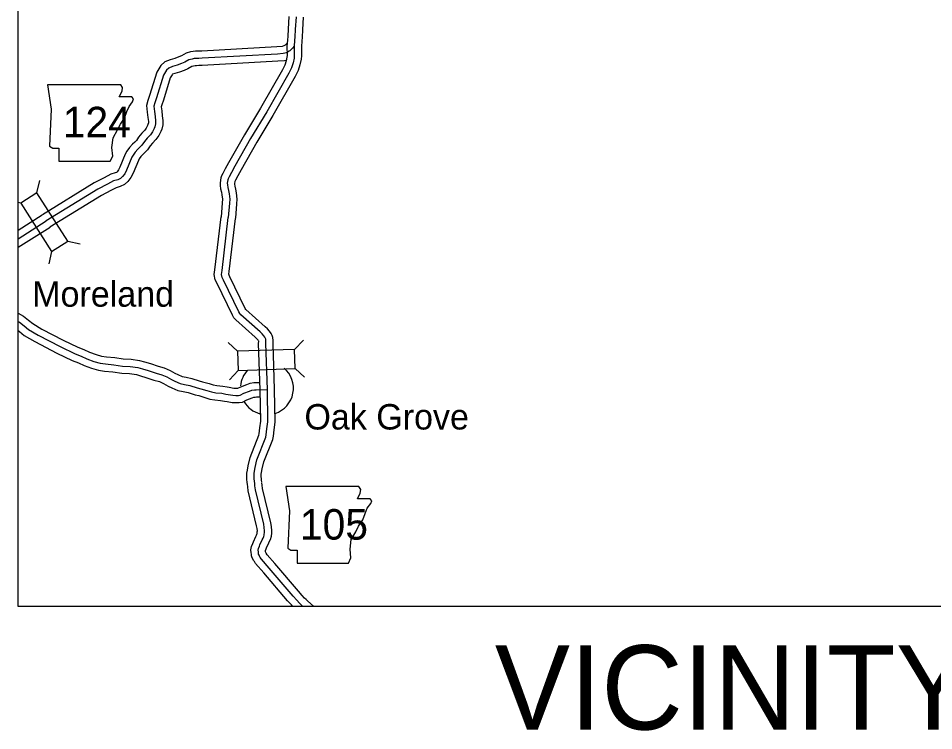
# Model space of a CAD drawing. Extents: x 1373862 to 1376999, y 1168398 to 1170455.
# Drawn here: x 1373884.5 to 1374264.4, y 1169674.5 to 1169970.4 of the extents above; entities that cross this region are included whole.
import ezdxf

# ---------------------------------------------------------------- set-up
doc = ezdxf.new("R2010")
doc.units = 0
for name, color, linetype in [('Level 10', 7, 'Continuous'), ('Level 20', 7, 'Continuous'), ('Level 21', 7, 'Continuous'), ('Level 24', 7, 'Continuous'), ('Level 59', 7, 'Continuous'), ('R_Draft', 7, 'Continuous')]:
    doc.layers.add(name, color=color, linetype=linetype)

msp = doc.modelspace()

# ---------------------------------------------------------------- linework, layer by layer
at = {"layer": 'Level 10'}
for points in [[(1373996.77, 1169971.05), (1373996.45, 1169965.88), (1373996.3, 1169962.9), (1373996.16, 1169961.33), (1373996, 1169958.83), (1373996.05, 1169954.92), (1373996, 1169954.28), (1373995.61, 1169952.66), (1373995.05, 1169950.89), (1373994.13, 1169948.96), (1373985, 1169933.02), (1373978.31, 1169921.99), (1373971.79, 1169910.4), (1373970.35, 1169907.8), (1373969.36, 1169905.9), (1373968.86, 1169904.91), (1373968.56, 1169904.04), (1373968.22, 1169902.08), (1373968.28, 1169900.92), (1373968.46, 1169899.55), (1373968.8, 1169898.18), (1373969, 1169897.06), (1373969.21, 1169895.2), (1373969.09, 1169893.76), (1373968.63, 1169887.8)], [(1374002.77, 1169970.84), (1374002.44, 1169965.54), (1374002.29, 1169962.47), (1374002.14, 1169960.87), (1374002, 1169958.68), (1374002.05, 1169954.73), (1374001.95, 1169953.33), (1374001.39, 1169951.04), (1374000.64, 1169948.7), (1373999.46, 1169946.18), (1373990.17, 1169929.98), (1373983.49, 1169918.96), (1373977.03, 1169907.47), (1373975.63, 1169904.96), (1373974.7, 1169903.16), (1373974.4, 1169902.58), (1373974.39, 1169902.55), (1373974.24, 1169901.7), (1373974.26, 1169901.47), (1373974.36, 1169900.68), (1373974.68, 1169899.42), (1373974.94, 1169897.91), (1373975.23, 1169895.29), (1373975.07, 1169893.28), (1373974.61, 1169887.34)], [(1373996.12, 1169959.97), (1373995.81, 1169959.7), (1373995.26, 1169959.18), (1373995.26, 1169959.18), (1373994.7, 1169958.88), (1373993.97, 1169958.68), (1373991.81, 1169958.52), (1373960.62, 1169956.76), (1373959.29, 1169956.73), (1373958.07, 1169956.68), (1373957.12, 1169956.58), (1373955.95, 1169956.38), (1373954.16, 1169955.9), (1373952.26, 1169954.83), (1373951.09, 1169954.33), (1373949.46, 1169953.73), (1373947.52, 1169953.16), (1373945.35, 1169952.31), (1373943.58, 1169950.78), (1373941.97, 1169947.97), (1373939, 1169938.24), (1373938.29, 1169936.17), (1373937.75, 1169934.18), (1373938.02, 1169931.33), (1373938.25, 1169929.15), (1373938.48, 1169927.56), (1373938.47, 1169926.91), (1373938.31, 1169926.25), (1373938.13, 1169925.85), (1373937.59, 1169924.75), (1373937, 1169923.88), (1373935.69, 1169922.63), (1373934.37, 1169920.97), (1373933.49, 1169919.61), (1373932.82, 1169918.97), (1373931.91, 1169918.08), (1373930.69, 1169916.7), (1373929.54, 1169915.13), (1373928.9, 1169913.9), (1373926.65, 1169908.48), (1373926.13, 1169907.43), (1373925.5, 1169906.64), (1373925.19, 1169906.34), (1373924.71, 1169906.13), (1373922.87, 1169905.6), (1373920.13, 1169904.13), (1373916.04, 1169901.96), (1373894.49, 1169888.74)], [(1373995.59, 1169952.9), (1373994.99, 1169952.73), (1373992.2, 1169952.54), (1373960.86, 1169950.76), (1373959.48, 1169950.73), (1373958.5, 1169950.69), (1373957.94, 1169950.63), (1373957.24, 1169950.51), (1373956.44, 1169950.3), (1373954.91, 1169949.44), (1373953.31, 1169948.75), (1373951.34, 1169948.03), (1373949.47, 1169947.48), (1373948.5, 1169947.1), (1373948.28, 1169946.9), (1373947.51, 1169945.57), (1373944.71, 1169936.39), (1373944.03, 1169934.41), (1373943.83, 1169933.66), (1373943.99, 1169931.92), (1373944.21, 1169929.9), (1373944.49, 1169927.91), (1373944.45, 1169926.11), (1373944.02, 1169924.35), (1373943.59, 1169923.34), (1373942.79, 1169921.72), (1373941.6, 1169919.99), (1373940.13, 1169918.57), (1373939.24, 1169917.46), (1373938.15, 1169915.77), (1373936.99, 1169914.65), (1373936.25, 1169913.94), (1373935.37, 1169912.94), (1373934.65, 1169911.95), (1373934.34, 1169911.35), (1373932.11, 1169905.99), (1373931.22, 1169904.2), (1373929.94, 1169902.58), (1373928.57, 1169901.28), (1373926.76, 1169900.48), (1373925.14, 1169900.01), (1373922.95, 1169898.84), (1373919.02, 1169896.75), (1373897.63, 1169883.63)], [(1373884.49, 1169882.37), (1373894.45, 1169888.71)], [(1373979.64, 1169776.67), (1373979.47, 1169777.75), (1373979.38, 1169778.85), (1373979.34, 1169779.81), (1373979.33, 1169781.5), (1373979.56, 1169782.74), (1373979.83, 1169784.42), (1373980.69, 1169787.93), (1373984.33, 1169797.23), (1373984.46, 1169797.8), (1373984.67, 1169800.2), (1373985.11, 1169803.02), (1373984.87, 1169816.04), (1373984.22, 1169835.35), (1373984.26, 1169836.32), (1373984.22, 1169836.4), (1373984.05, 1169836.64), (1373983.51, 1169837.24), (1373982.85, 1169837.9), (1373974.72, 1169845.12), (1373973.94, 1169845.99), (1373973.37, 1169847.06), (1373966.97, 1169860.25), (1373966.19, 1169861.74), (1373965.82, 1169863.91), (1373966.06, 1169865.91), (1373968.64, 1169887.92)], [(1373985.56, 1169777.64), (1373985.43, 1169778.48), (1373985.37, 1169779.22), (1373985.34, 1169779.94), (1373985.34, 1169780.97), (1373985.47, 1169781.73), (1373985.71, 1169783.23), (1373986.42, 1169786.11), (1373990.08, 1169795.47), (1373990.4, 1169796.87), (1373990.63, 1169799.48), (1373991.12, 1169802.6), (1373990.87, 1169816.19), (1373990.22, 1169835.33), (1373990.27, 1169836.52), (1373990.13, 1169837.85), (1373989.8, 1169838.63), (1373989.42, 1169839.43), (1373988.77, 1169840.38), (1373987.85, 1169841.39), (1373986.96, 1169842.27), (1373978.95, 1169849.39), (1373978.88, 1169849.46), (1373978.71, 1169849.78), (1373972.33, 1169862.95), (1373971.95, 1169863.68), (1373971.88, 1169864.06), (1373972.02, 1169865.2), (1373974.6, 1169887.23)], [(1373884.49, 1169875.26), (1373897.67, 1169883.65)], [(1373884.49, 1169847.96), (1373886.62, 1169846.59), (1373888.77, 1169845), (1373890.46, 1169843.55), (1373894.23, 1169841.31), (1373903.14, 1169836.68), (1373909.19, 1169833.75), (1373911.74, 1169832.81), (1373914.07, 1169831.76), (1373916.76, 1169830.73), (1373919.03, 1169830.08), (1373921.05, 1169829.81), (1373924.54, 1169829.41), (1373928.06, 1169828.93), (1373931.27, 1169828.78), (1373934.75, 1169828.25), (1373936.89, 1169827.68), (1373939.3, 1169826.93), (1373942.54, 1169825.84), (1373945.07, 1169825.15), (1373947.52, 1169824.08), (1373949.42, 1169822.95), (1373950.64, 1169822.41), (1373952.52, 1169821.58), (1373954.12, 1169821.27), (1373956.53, 1169820.75), (1373959.55, 1169819.77), (1373960.97, 1169819.42), (1373963.66, 1169818.64), (1373965.41, 1169818.09), (1373966.86, 1169817.85), (1373969.37, 1169817.6), (1373971.11, 1169817.24), (1373972.05, 1169817.1), (1373973.88, 1169816.8), (1373974.81, 1169816.75), (1373975.63, 1169816.75), (1373975.65, 1169816.75), (1373976.88, 1169817.36), (1373979.37, 1169818.33), (1373980.74, 1169818.84), (1373982.21, 1169819.04), (1373983.18, 1169819.08), (1373984.82, 1169819.09)], [(1373884.49, 1169840.71), (1373885.03, 1169840.31), (1373886.95, 1169838.66), (1373891.32, 1169836.07), (1373900.45, 1169831.32), (1373906.84, 1169828.22), (1373909.47, 1169827.25), (1373911.77, 1169826.22), (1373914.87, 1169825.03), (1373917.81, 1169824.19), (1373920.31, 1169823.86), (1373923.78, 1169823.46), (1373927.51, 1169822.95), (1373930.68, 1169822.8), (1373933.53, 1169822.37), (1373935.23, 1169821.92), (1373937.45, 1169821.22), (1373940.79, 1169820.1), (1373943.07, 1169819.48), (1373944.77, 1169818.73), (1373946.66, 1169817.61), (1373948.21, 1169816.92), (1373950.72, 1169815.82), (1373952.92, 1169815.39), (1373954.96, 1169814.95), (1373957.92, 1169813.99), (1373959.42, 1169813.63), (1373961.91, 1169812.9), (1373964.01, 1169812.23), (1373966.08, 1169811.89), (1373968.46, 1169811.66), (1373970.07, 1169811.32), (1373971.14, 1169811.17), (1373973.23, 1169810.82), (1373974.66, 1169810.75), (1373976.11, 1169810.75), (1373977.49, 1169810.97), (1373979.3, 1169811.86), (1373981.5, 1169812.72), (1373982.19, 1169812.98), (1373982.75, 1169813.05), (1373983.33, 1169813.08), (1373984.73, 1169813.09)], [(1373998.42, 1169726), (1373997.84, 1169726.68), (1373996.28, 1169728.41), (1373986.34, 1169740.02), (1373982.99, 1169743.9), (1373982.47, 1169744.7), (1373982.18, 1169745.07), (1373981.6, 1169746.26), (1373981.32, 1169747.13), (1373981.21, 1169747.77), (1373981.12, 1169748.37), (1373981.03, 1169749.63), (1373981.31, 1169751.02), (1373981.78, 1169752.25), (1373982.04, 1169752.86), (1373983.03, 1169755.11), (1373983.35, 1169755.72), (1373983.51, 1169756.09), (1373983.59, 1169756.43), (1373983.63, 1169756.56), (1373983.67, 1169757.01), (1373983.7, 1169757.43), (1373983.59, 1169758.5), (1373983.41, 1169759.6), (1373979.95, 1169774.03), (1373979.74, 1169775.77), (1373979.62, 1169776.82)], [(1374007.18, 1169726), (1374004.46, 1169728.46), (1374003.94, 1169728.93), (1374003.32, 1169729.5), (1374002.35, 1169730.64), (1374000.78, 1169732.37), (1373990.89, 1169743.93), (1373987.8, 1169747.5), (1373987.38, 1169748.17), (1373987.3, 1169748.27), (1373987.18, 1169748.51), (1373987.16, 1169748.55), (1373987.14, 1169748.71), (1373987.09, 1169749.03), (1373987.07, 1169749.25), (1373987.09, 1169749.35), (1373987.35, 1169750.01), (1373987.55, 1169750.48), (1373988.44, 1169752.51), (1373988.78, 1169753.15), (1373989.24, 1169754.23), (1373989.38, 1169754.86), (1373989.53, 1169755.33), (1373989.65, 1169756.49), (1373989.72, 1169757.55), (1373989.54, 1169759.31), (1373989.29, 1169760.81), (1373985.87, 1169775.09), (1373985.7, 1169776.46), (1373985.58, 1169777.49)]]:
    msp.add_lwpolyline(points, dxfattribs=at)
at = {"layer": 'Level 20'}
for p, q in [((1373892.23, 1169897.83), (1373893.37, 1169902.98)), ((1373885.55, 1169893.58), (1373884.49, 1169893.81)), ((1373904.99, 1169877.79), (1373910.15, 1169876.65)), ((1373898.31, 1169873.54), (1373897.17, 1169868.38)), ((1373975.45, 1169832.04), (1373971.59, 1169835.64)), ((1373999.19, 1169832.84), (1374002.8, 1169836.69)), ((1373999.46, 1169824.92), (1374003.32, 1169821.31)), ((1373975.71, 1169824.12), (1373972.11, 1169820.26))]:
    msp.add_line(p, q, dxfattribs=at)
for points in [[(1373885.55, 1169893.58), (1373898.31, 1169873.54), (1373904.99, 1169877.79), (1373892.23, 1169897.83)], [(1373975.71, 1169824.12), (1373999.46, 1169824.92), (1373999.19, 1169832.84), (1373975.45, 1169832.04)]]:
    msp.add_lwpolyline(points, close=True, dxfattribs=at)
at = {"layer": 'Level 21'}
for points in [[(1373896.59, 1169942.77), (1373898.11, 1169932.62), (1373897.44, 1169917.22), (1373898.79, 1169916.37), (1373901.33, 1169916.37), (1373901.33, 1169910.96), (1373922.64, 1169910.96), (1373923.66, 1169913.16), (1373923.32, 1169916.71), (1373923.83, 1169920.77), (1373925.69, 1169923.99), (1373926.87, 1169926.36), (1373928.57, 1169928.89), (1373929.58, 1169931.6), (1373930.43, 1169933.8), (1373931.95, 1169935.66), (1373932.29, 1169936.85), (1373931.61, 1169937.69), (1373926.37, 1169937.69), (1373927.55, 1169940.06), (1373927.72, 1169941.58), (1373927.02, 1169942.75)], [(1373995.46, 1169775.88), (1373996.98, 1169765.73), (1373996.3, 1169750.33), (1373997.66, 1169749.48), (1374000.19, 1169749.48), (1374000.19, 1169744.07), (1374021.51, 1169744.07), (1374022.53, 1169746.27), (1374022.19, 1169749.82), (1374022.69, 1169753.88), (1374024.56, 1169757.1), (1374025.74, 1169759.47), (1374027.43, 1169762), (1374028.45, 1169764.71), (1374029.29, 1169766.91), (1374030.82, 1169768.77), (1374031.15, 1169769.96), (1374030.48, 1169770.8), (1374025.23, 1169770.8), (1374026.42, 1169773.17), (1374026.59, 1169774.69), (1374025.88, 1169775.86)]]:
    msp.add_lwpolyline(points, close=True, dxfattribs=at)
at = {"layer": 'Level 24'}
for start, end in [(288.4119, 49.6434), (137.3818, 174.7553), (210.7252, 254.7143)]:
    msp.add_arc((1373987.68, 1169816.71), 11, start, end, dxfattribs=at)
at = {"layer": 'Level 59'}
for points in [[(1373999.77, 1169970.95), (1373999.45, 1169965.71), (1373999.29, 1169962.68), (1373999.15, 1169961.1), (1373999, 1169958.75), (1373999.05, 1169954.83), (1373998.97, 1169953.81), (1373998.5, 1169951.85), (1373997.85, 1169949.79), (1373996.8, 1169947.57), (1373987.59, 1169931.5), (1373980.9, 1169920.47), (1373974.41, 1169908.93), (1373972.99, 1169906.38), (1373972.03, 1169904.53), (1373971.63, 1169903.74), (1373971.48, 1169903.3), (1373971.23, 1169901.89), (1373971.27, 1169901.19), (1373971.41, 1169900.11), (1373971.74, 1169898.8), (1373971.97, 1169897.48), (1373972.22, 1169895.24), (1373972.08, 1169893.52), (1373971.62, 1169887.57)], [(1373999, 1169958.75), (1373998.3, 1169957.9), (1373997.83, 1169957.48), (1373997.23, 1169956.91), (1373996.91, 1169956.66), (1373995.83, 1169956.08), (1373994.48, 1169955.71), (1373992, 1169955.53), (1373960.74, 1169953.76), (1373959.38, 1169953.73), (1373958.29, 1169953.68), (1373957.53, 1169953.61), (1373956.59, 1169953.45), (1373955.3, 1169953.1), (1373953.59, 1169952.14), (1373952.2, 1169951.54), (1373950.4, 1169950.88), (1373948.49, 1169950.32), (1373946.93, 1169949.7), (1373945.93, 1169948.84), (1373944.74, 1169946.77), (1373941.85, 1169937.31), (1373941.16, 1169935.29), (1373940.79, 1169933.92), (1373941, 1169931.63), (1373941.23, 1169929.53), (1373941.49, 1169927.73), (1373941.46, 1169926.51), (1373941.16, 1169925.3), (1373940.86, 1169924.59), (1373940.19, 1169923.24), (1373939.3, 1169921.93), (1373937.91, 1169920.6), (1373936.81, 1169919.21), (1373935.82, 1169917.69), (1373934.9, 1169916.81), (1373934.08, 1169916.01), (1373933.03, 1169914.82), (1373932.1, 1169913.54), (1373931.62, 1169912.63), (1373929.38, 1169907.23), (1373928.68, 1169905.81), (1373927.72, 1169904.61), (1373926.88, 1169903.81), (1373925.74, 1169903.3), (1373924.01, 1169902.8), (1373921.54, 1169901.49), (1373917.53, 1169899.35), (1373896.06, 1169886.18)], [(1373884.49, 1169878.81), (1373896.06, 1169886.18)], [(1373982.6, 1169777.16), (1373982.45, 1169778.11), (1373982.37, 1169779.03), (1373982.34, 1169779.87), (1373982.33, 1169781.23), (1373982.52, 1169782.24), (1373982.77, 1169783.82), (1373983.55, 1169787.02), (1373987.21, 1169796.35), (1373987.43, 1169797.33), (1373987.65, 1169799.84), (1373988.11, 1169802.81), (1373987.87, 1169816.12), (1373987.22, 1169835.34), (1373987.26, 1169836.42), (1373987.19, 1169837.1), (1373987.07, 1169837.4), (1373986.82, 1169837.92), (1373986.41, 1169838.51), (1373985.68, 1169839.32), (1373984.91, 1169840.08), (1373976.84, 1169847.25), (1373976.41, 1169847.73), (1373976.04, 1169848.42), (1373969.65, 1169861.6), (1373969.07, 1169862.71), (1373968.85, 1169863.99), (1373969.04, 1169865.55), (1373971.62, 1169887.57)], [(1373884.49, 1169844.4), (1373884.92, 1169844.12), (1373886.9, 1169842.65), (1373888.7, 1169841.1), (1373892.77, 1169838.69), (1373901.8, 1169834), (1373908.02, 1169830.98), (1373910.61, 1169830.03), (1373912.92, 1169828.99), (1373915.81, 1169827.88), (1373918.42, 1169827.14), (1373920.68, 1169826.84), (1373924.16, 1169826.44), (1373927.78, 1169825.94), (1373930.98, 1169825.79), (1373934.14, 1169825.31), (1373936.06, 1169824.8), (1373938.37, 1169824.08), (1373941.66, 1169822.97), (1373944.07, 1169822.31), (1373946.14, 1169821.41), (1373948.04, 1169820.28), (1373949.43, 1169819.66), (1373951.62, 1169818.7), (1373953.52, 1169818.33), (1373955.74, 1169817.85), (1373958.73, 1169816.88), (1373960.2, 1169816.52), (1373962.78, 1169815.77), (1373964.71, 1169815.16), (1373966.47, 1169814.87), (1373968.91, 1169814.63), (1373970.59, 1169814.28), (1373971.59, 1169814.14), (1373973.56, 1169813.81), (1373974.74, 1169813.75), (1373975.87, 1169813.75), (1373976.57, 1169813.86), (1373978.09, 1169814.61), (1373980.43, 1169815.53), (1373981.46, 1169815.91), (1373982.48, 1169816.04), (1373983.26, 1169816.08), (1373987.87, 1169816.12)], [(1374002.71, 1169726), (1374002.45, 1169726.24), (1374001.93, 1169726.71), (1374001.16, 1169727.41), (1374000.1, 1169728.66), (1373998.53, 1169730.39), (1373988.61, 1169741.97), (1373985.4, 1169745.7), (1373984.92, 1169746.43), (1373984.74, 1169746.67), (1373984.39, 1169747.38), (1373984.24, 1169747.84), (1373984.17, 1169748.24), (1373984.11, 1169748.7), (1373984.05, 1169749.44), (1373984.2, 1169750.18), (1373984.56, 1169751.13), (1373984.79, 1169751.67), (1373985.74, 1169753.81), (1373986.06, 1169754.44), (1373986.37, 1169755.16), (1373986.48, 1169755.65), (1373986.58, 1169755.95), (1373986.66, 1169756.75), (1373986.71, 1169757.49), (1373986.57, 1169758.91), (1373986.35, 1169760.21), (1373982.91, 1169774.56), (1373982.72, 1169776.12), (1373982.6, 1169777.16)]]:
    msp.add_lwpolyline(points, dxfattribs=at)
at = {"layer": 'R_Draft'}
msp.add_lwpolyline([(1373884.49, 1170361.65), (1374614.47, 1170361.65), (1374614.47, 1169726), (1373884.49, 1169726)], close=True, dxfattribs=at)

# ---------------------------------------------------------------- texts
at = {"layer": 'Level 21'}
for s, p in [('124', (1373902.93, 1169920.94)), ('105', (1374001.35, 1169753.84))]:
    msp.add_text(s, height=12.672, dxfattribs=at).set_placement(p)
at = {"layer": 'Level 24'}
for s, p in [('Moreland', (1373890.25, 1169850.58)), ('Oak Grove', (1374003.24, 1169799.57))]:
    msp.add_text(s, height=10.56, dxfattribs=at).set_placement(p)
at = {"layer": 'R_Draft'}
msp.add_text('VICINITY MAP', height=35, dxfattribs=at).set_placement((1374082.26, 1169674.96))

doc.saveas('drawing.dxf')
